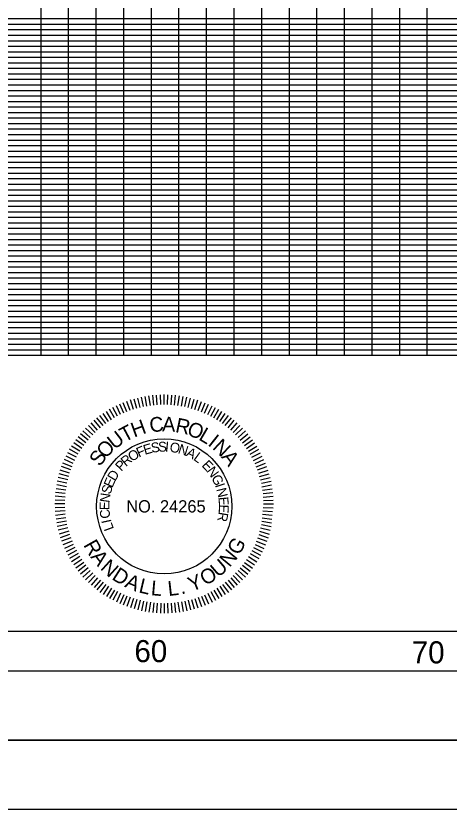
# Model space of a CAD drawing. Extents: x -15 to 165, y -6 to 109.
# Drawn here: x 135.09 to 150.79, y -6.45 to 22.3 of the extents above; entities that cross this region are included whole.
import ezdxf

# ---------------------------------------------------------------- set-up
doc = ezdxf.new("R2010")
doc.units = 0
for name, color, linetype in [('RD_SHT_Bndy', 7, 'Continuous'), ('RD_SHT_Iplotshp', 7, 'Continuous'), ('RD_SHT_MjGrid', 7, 'Continuous'), ('RD_SHT_MnGrid', 7, 'Continuous'), ('RD_SHT_SubGrid', 7, 'Continuous'), ('RD_SHT_TX', 7, 'Continuous'), ('RD_TX_PEShield', 7, 'Continuous')]:
    doc.layers.add(name, color=color, linetype=linetype)

msp = doc.modelspace()

# ---------------------------------------------------------------- linework, layer by layer
at = {"layer": 'RD_SHT_Bndy'}
for p, q in [((-12.73, -3.949), (163.27, -3.949)), ((-12.73, -6.449), (163.27, -6.449))]:
    msp.add_line(p, q, dxfattribs=at)
msp.add_lwpolyline([(-4.99, 103.551), (162.51, 103.551), (162.51, -1.449), (-4.99, -1.449)], close=True, dxfattribs=at)
at = {"layer": 'RD_SHT_Iplotshp'}
msp.add_lwpolyline([(-14.589, 106.051), (165.01, 106.051), (165.01, -3.949), (-14.589, -3.949)], close=True, dxfattribs=at)
at = {"layer": 'RD_SHT_MjGrid'}
for p, q in [((140, 10), (140, 100)), ((145, 10), (145, 100)), ((150, 10), (150, 100)), ((0, 20), (160, 20)), ((0, 15), (160, 15)), ((0, 10), (160, 10)), ((0, 0), (160, 0))]:
    msp.add_line(p, q, dxfattribs=at)
at = {"layer": 'RD_SHT_MnGrid'}
for p, q in [((136, 10), (136, 100)), ((137, 10), (137, 100)), ((138, 10), (138, 100)), ((139, 10), (139, 100)), ((141, 10), (141, 100)), ((142, 10), (142, 100)), ((143, 10), (143, 100)), ((144, 10), (144, 100)), ((146, 10), (146, 100)), ((147, 10), (147, 100)), ((148, 10), (148, 100)), ((149, 10), (149, 100)), ((0, 22), (160, 22)), ((0, 21), (160, 21)), ((0, 19), (160, 19)), ((0, 18), (160, 18)), ((0, 17), (160, 17)), ((0, 16), (160, 16)), ((0, 14), (160, 14)), ((0, 13), (160, 13)), ((0, 12), (160, 12)), ((0, 11), (160, 11))]:
    msp.add_line(p, q, dxfattribs=at)
at = {"layer": 'RD_SHT_SubGrid'}
for p, q in [((0, 22.2), (160, 22.2)), ((0, 21.8), (160, 21.8)), ((0, 21.6), (160, 21.6)), ((0, 21.4), (160, 21.4)), ((0, 21.2), (160, 21.2)), ((0, 20.8), (160, 20.8)), ((0, 20.6), (160, 20.6)), ((0, 20.4), (160, 20.4)), ((0, 20.2), (160, 20.2)), ((0, 19.8), (160, 19.8)), ((0, 19.6), (160, 19.6)), ((0, 19.4), (160, 19.4)), ((0, 19.2), (160, 19.2)), ((0, 18.8), (160, 18.8)), ((0, 18.6), (160, 18.6)), ((0, 18.4), (160, 18.4)), ((0, 18.2), (160, 18.2)), ((0, 17.8), (160, 17.8)), ((0, 17.6), (160, 17.6)), ((0, 17.4), (160, 17.4)), ((0, 17.2), (160, 17.2)), ((0, 16.8), (160, 16.8)), ((0, 16.6), (160, 16.6)), ((0, 16.4), (160, 16.4)), ((0, 16.2), (160, 16.2)), ((0, 15.8), (160, 15.8)), ((0, 15.6), (160, 15.6)), ((0, 15.4), (160, 15.4)), ((0, 15.2), (160, 15.2)), ((0, 14.8), (160, 14.8)), ((0, 14.6), (160, 14.6)), ((0, 14.4), (160, 14.4)), ((0, 14.2), (160, 14.2)), ((0, 13.8), (160, 13.8)), ((0, 13.6), (160, 13.6)), ((0, 13.4), (160, 13.4)), ((0, 13.2), (160, 13.2)), ((0, 12.8), (160, 12.8)), ((0, 12.6), (160, 12.6)), ((0, 12.4), (160, 12.4)), ((0, 12.2), (160, 12.2)), ((0, 11.8), (160, 11.8)), ((0, 11.6), (160, 11.6)), ((0, 11.4), (160, 11.4)), ((0, 11.2), (160, 11.2)), ((0, 10.8), (160, 10.8)), ((0, 10.6), (160, 10.6)), ((0, 10.4), (160, 10.4)), ((0, 10.2), (160, 10.2))]:
    msp.add_line(p, q, dxfattribs=at)
at = {"layer": 'RD_TX_PEShield'}
for p, q in [((139.349, 8.04), (139.239, 8.379)), ((139.349, 8.04), (139.239, 8.379)), ((139.47, 8.073), (139.372, 8.414)), ((139.47, 8.073), (139.372, 8.414)), ((139.592, 8.105), (139.506, 8.45)), ((139.592, 8.105), (139.506, 8.45)), ((139.713, 8.138), (139.639, 8.486)), ((139.713, 8.138), (139.639, 8.486)), ((139.838, 8.157), (139.776, 8.508)), ((139.838, 8.157), (139.776, 8.508)), ((139.962, 8.177), (139.912, 8.529)), ((139.962, 8.177), (139.912, 8.529)), ((140.086, 8.197), (140.049, 8.551)), ((140.086, 8.197), (140.049, 8.551)), ((140.212, 8.203), (140.187, 8.558)), ((140.212, 8.203), (140.187, 8.558)), ((140.337, 8.21), (140.325, 8.565)), ((140.337, 8.21), (140.325, 8.565)), ((140.463, 8.217), (140.463, 8.573)), ((140.463, 8.217), (140.463, 8.573)), ((140.588, 8.21), (140.601, 8.565)), ((140.588, 8.21), (140.601, 8.565)), ((140.714, 8.203), (140.739, 8.558)), ((140.714, 8.203), (140.739, 8.558)), ((140.84, 8.197), (140.877, 8.551)), ((140.84, 8.197), (140.877, 8.551)), ((140.964, 8.177), (141.013, 8.529)), ((140.964, 8.177), (141.013, 8.529)), ((141.088, 8.157), (141.15, 8.508)), ((141.088, 8.157), (141.15, 8.508)), ((141.212, 8.138), (141.286, 8.486)), ((141.212, 8.138), (141.286, 8.486)), ((141.212, 8.138), (141.286, 8.486)), ((141.334, 8.105), (141.42, 8.45)), ((141.334, 8.105), (141.42, 8.45)), ((141.334, 8.105), (141.42, 8.45)), ((141.455, 8.073), (141.553, 8.414)), ((141.455, 8.073), (141.553, 8.414)), ((141.455, 8.073), (141.553, 8.414)), ((141.577, 8.04), (141.687, 8.379)), ((141.577, 8.04), (141.687, 8.379)), ((141.577, 8.04), (141.687, 8.379)), ((138.773, 7.791), (138.606, 8.105)), ((138.773, 7.791), (138.606, 8.105)), ((138.885, 7.848), (138.729, 8.167)), ((138.885, 7.848), (138.729, 8.167)), ((138.997, 7.905), (138.852, 8.23)), ((138.997, 7.905), (138.852, 8.23)), ((139.114, 7.95), (138.981, 8.28)), ((139.114, 7.95), (138.981, 8.28)), ((139.231, 7.995), (139.11, 8.329)), ((139.231, 7.995), (139.11, 8.329)), ((141.694, 7.995), (141.816, 8.329)), ((141.694, 7.995), (141.816, 8.329)), ((141.694, 7.995), (141.816, 8.329)), ((141.811, 7.95), (141.945, 8.28)), ((141.811, 7.95), (141.945, 8.28)), ((141.811, 7.95), (141.945, 8.28)), ((141.929, 7.905), (142.074, 8.23)), ((141.929, 7.905), (142.074, 8.23)), ((141.929, 7.905), (142.074, 8.23)), ((142.041, 7.848), (142.197, 8.167)), ((142.041, 7.848), (142.197, 8.167)), ((142.041, 7.848), (142.197, 8.167)), ((142.153, 7.791), (142.32, 8.105)), ((142.153, 7.791), (142.32, 8.105)), ((142.153, 7.791), (142.32, 8.105)), ((138.344, 7.528), (138.135, 7.816)), ((138.344, 7.528), (138.135, 7.816)), ((138.45, 7.597), (138.251, 7.891)), ((138.45, 7.597), (138.251, 7.891)), ((138.555, 7.665), (138.367, 7.967)), ((138.555, 7.665), (138.367, 7.967)), ((138.661, 7.734), (138.483, 8.042)), ((138.661, 7.734), (138.483, 8.042)), ((142.265, 7.734), (142.443, 8.042)), ((142.265, 7.734), (142.443, 8.042)), ((142.265, 7.734), (142.443, 8.042)), ((142.371, 7.665), (142.559, 7.967)), ((142.371, 7.665), (142.559, 7.967)), ((142.371, 7.665), (142.559, 7.967)), ((142.476, 7.597), (142.675, 7.891)), ((142.476, 7.597), (142.675, 7.891)), ((142.476, 7.597), (142.675, 7.891)), ((142.581, 7.528), (142.791, 7.816)), ((142.581, 7.528), (142.791, 7.816)), ((142.581, 7.528), (142.791, 7.816)), ((138.051, 7.291), (137.813, 7.555)), ((138.051, 7.291), (137.813, 7.555)), ((138.149, 7.37), (137.92, 7.642)), ((138.149, 7.37), (137.92, 7.642)), ((138.246, 7.449), (138.027, 7.729)), ((138.246, 7.449), (138.027, 7.729)), ((142.679, 7.449), (142.898, 7.729)), ((142.679, 7.449), (142.898, 7.729)), ((142.679, 7.449), (142.898, 7.729)), ((142.777, 7.37), (143.005, 7.642)), ((142.777, 7.37), (143.005, 7.642)), ((142.777, 7.37), (143.005, 7.642)), ((142.875, 7.291), (143.113, 7.555)), ((142.875, 7.291), (143.113, 7.555)), ((142.875, 7.291), (143.113, 7.555)), ((137.784, 7.024), (137.52, 7.262)), ((137.784, 7.024), (137.52, 7.262)), ((137.873, 7.113), (137.617, 7.36)), ((137.873, 7.113), (137.617, 7.36)), ((137.962, 7.202), (137.715, 7.457)), ((137.962, 7.202), (137.715, 7.457)), ((142.964, 7.202), (143.211, 7.457)), ((142.964, 7.202), (143.211, 7.457)), ((142.964, 7.202), (143.211, 7.457)), ((143.052, 7.113), (143.308, 7.36)), ((143.052, 7.113), (143.308, 7.36)), ((143.052, 7.113), (143.308, 7.36)), ((143.141, 7.024), (143.406, 7.262)), ((143.141, 7.024), (143.406, 7.262)), ((143.141, 7.024), (143.406, 7.262)), ((137.547, 6.731), (137.259, 6.94)), ((137.547, 6.731), (137.259, 6.94)), ((137.626, 6.828), (137.346, 7.047)), ((137.626, 6.828), (137.346, 7.047)), ((137.705, 6.926), (137.433, 7.155)), ((137.705, 6.926), (137.433, 7.155)), ((143.221, 6.926), (143.493, 7.155)), ((143.221, 6.926), (143.493, 7.155)), ((143.221, 6.926), (143.493, 7.155)), ((143.3, 6.828), (143.58, 7.047)), ((143.3, 6.828), (143.58, 7.047)), ((143.3, 6.828), (143.58, 7.047)), ((143.379, 6.731), (143.667, 6.94)), ((143.379, 6.731), (143.667, 6.94)), ((143.379, 6.731), (143.667, 6.94)), ((137.41, 6.52), (137.108, 6.708)), ((137.41, 6.52), (137.108, 6.708)), ((137.478, 6.625), (137.183, 6.824)), ((137.478, 6.625), (137.183, 6.824)), ((143.447, 6.625), (143.742, 6.824)), ((143.447, 6.625), (143.742, 6.824)), ((143.447, 6.625), (143.742, 6.824)), ((143.516, 6.52), (143.817, 6.708)), ((143.516, 6.52), (143.817, 6.708)), ((143.516, 6.52), (143.817, 6.708)), ((137.227, 6.19), (136.907, 6.346)), ((137.227, 6.19), (136.907, 6.346)), ((137.284, 6.302), (136.97, 6.469)), ((137.284, 6.302), (136.97, 6.469)), ((137.341, 6.414), (137.033, 6.592)), ((137.341, 6.414), (137.033, 6.592)), ((143.584, 6.414), (143.893, 6.592)), ((143.584, 6.414), (143.893, 6.592)), ((143.584, 6.414), (143.893, 6.592)), ((143.641, 6.302), (143.955, 6.469)), ((143.641, 6.302), (143.955, 6.469)), ((143.641, 6.302), (143.955, 6.469)), ((143.699, 6.19), (144.018, 6.346)), ((143.699, 6.19), (144.018, 6.346)), ((143.699, 6.19), (144.018, 6.346)), ((137.125, 5.961), (136.795, 6.094)), ((137.125, 5.961), (136.795, 6.094)), ((137.17, 6.078), (136.845, 6.223)), ((137.17, 6.078), (136.845, 6.223)), ((143.756, 6.078), (144.081, 6.223)), ((143.756, 6.078), (144.081, 6.223)), ((143.756, 6.078), (144.081, 6.223)), ((143.801, 5.961), (144.13, 6.094)), ((143.801, 5.961), (144.13, 6.094)), ((143.801, 5.961), (144.13, 6.094)), ((137.035, 5.726), (136.696, 5.836)), ((137.035, 5.726), (136.696, 5.836)), ((137.08, 5.843), (136.746, 5.965)), ((137.08, 5.843), (136.746, 5.965)), ((143.846, 5.843), (144.18, 5.965)), ((143.846, 5.843), (144.18, 5.965)), ((143.846, 5.843), (144.18, 5.965)), ((143.891, 5.726), (144.229, 5.836)), ((143.891, 5.726), (144.229, 5.836)), ((143.891, 5.726), (144.229, 5.836)), ((136.97, 5.483), (136.625, 5.569)), ((136.97, 5.483), (136.625, 5.569)), ((137.002, 5.604), (136.66, 5.702)), ((137.002, 5.604), (136.66, 5.702)), ((143.923, 5.604), (144.265, 5.702)), ((143.923, 5.604), (144.265, 5.702)), ((143.923, 5.604), (144.265, 5.702)), ((143.956, 5.483), (144.301, 5.569)), ((143.956, 5.483), (144.301, 5.569)), ((143.956, 5.483), (144.301, 5.569)), ((136.917, 5.237), (136.567, 5.299)), ((136.917, 5.237), (136.567, 5.299)), ((136.937, 5.361), (136.589, 5.435)), ((136.937, 5.361), (136.589, 5.435)), ((143.988, 5.361), (144.337, 5.435)), ((143.988, 5.361), (144.337, 5.435)), ((143.988, 5.361), (144.337, 5.435)), ((144.008, 5.237), (144.358, 5.299)), ((144.008, 5.237), (144.358, 5.299)), ((144.008, 5.237), (144.358, 5.299)), ((136.871, 4.863), (136.517, 4.888)), ((136.871, 4.863), (136.517, 4.888)), ((136.878, 4.989), (136.524, 5.026)), ((136.878, 4.989), (136.524, 5.026)), ((136.898, 5.113), (136.546, 5.163)), ((136.898, 5.113), (136.546, 5.163)), ((144.028, 5.113), (144.38, 5.163)), ((144.028, 5.113), (144.38, 5.163)), ((144.028, 5.113), (144.38, 5.163)), ((144.048, 4.989), (144.402, 5.026)), ((144.048, 4.989), (144.402, 5.026)), ((144.048, 4.989), (144.402, 5.026)), ((144.054, 4.863), (144.409, 4.888)), ((144.054, 4.863), (144.409, 4.888)), ((144.054, 4.863), (144.409, 4.888)), ((136.858, 4.612), (136.502, 4.612)), ((136.858, 4.612), (136.502, 4.612)), ((136.865, 4.738), (136.509, 4.75)), ((136.865, 4.738), (136.509, 4.75)), ((144.061, 4.738), (144.416, 4.75)), ((144.061, 4.738), (144.416, 4.75)), ((144.061, 4.738), (144.416, 4.75)), ((144.067, 4.612), (144.423, 4.612)), ((144.067, 4.612), (144.423, 4.612)), ((144.067, 4.612), (144.423, 4.612)), ((136.865, 4.486), (136.509, 4.474)), ((136.865, 4.486), (136.509, 4.474)), ((136.871, 4.361), (136.517, 4.336)), ((136.871, 4.361), (136.517, 4.336)), ((144.041, 4.362), (144.394, 4.337)), ((144.041, 4.362), (144.394, 4.337)), ((144.054, 4.487), (144.409, 4.474)), ((144.054, 4.487), (144.409, 4.474)), ((136.878, 4.235), (136.524, 4.198)), ((136.878, 4.235), (136.524, 4.198)), ((136.898, 4.111), (136.546, 4.061)), ((136.898, 4.111), (136.546, 4.061)), ((144.015, 4.113), (144.366, 4.063)), ((144.015, 4.113), (144.366, 4.063)), ((144.028, 4.237), (144.38, 4.2)), ((144.028, 4.237), (144.38, 4.2)), ((136.917, 3.987), (136.567, 3.925)), ((136.917, 3.987), (136.567, 3.925)), ((136.937, 3.863), (136.589, 3.789)), ((136.937, 3.863), (136.589, 3.789)), ((136.97, 3.741), (136.625, 3.655)), ((136.97, 3.741), (136.625, 3.655)), ((143.956, 3.741), (144.301, 3.655)), ((143.956, 3.741), (144.301, 3.655)), ((143.988, 3.863), (144.337, 3.789)), ((143.988, 3.863), (144.337, 3.789)), ((144.002, 3.988), (144.351, 3.926)), ((144.002, 3.988), (144.351, 3.926)), ((137.002, 3.62), (136.66, 3.522)), ((137.002, 3.62), (136.66, 3.522)), ((137.035, 3.498), (136.696, 3.388)), ((143.891, 3.498), (144.229, 3.388)), ((143.891, 3.498), (144.229, 3.388)), ((143.923, 3.62), (144.265, 3.522)), ((143.923, 3.62), (144.265, 3.522)), ((137.08, 3.381), (136.746, 3.259)), ((137.08, 3.381), (136.746, 3.259)), ((137.125, 3.263), (136.795, 3.13)), ((137.125, 3.263), (136.795, 3.13)), ((143.801, 3.263), (144.13, 3.13)), ((143.801, 3.263), (144.13, 3.13)), ((143.846, 3.381), (144.18, 3.259)), ((143.846, 3.381), (144.18, 3.259)), ((137.17, 3.146), (136.845, 3.001)), ((137.17, 3.146), (136.845, 3.001)), ((137.227, 3.034), (136.907, 2.878)), ((137.227, 3.034), (136.907, 2.878)), ((137.284, 2.922), (136.97, 2.755)), ((137.284, 2.922), (136.97, 2.755)), ((143.641, 2.922), (143.955, 2.755)), ((143.641, 2.922), (143.955, 2.755)), ((143.699, 3.034), (144.018, 2.878)), ((143.699, 3.034), (144.018, 2.878)), ((143.756, 3.146), (144.081, 3.001)), ((143.756, 3.146), (144.081, 3.001)), ((137.341, 2.81), (137.033, 2.632)), ((137.341, 2.81), (137.033, 2.632)), ((137.41, 2.704), (137.108, 2.516)), ((137.41, 2.704), (137.108, 2.516)), ((137.478, 2.599), (137.183, 2.4)), ((137.478, 2.599), (137.183, 2.4)), ((143.447, 2.599), (143.742, 2.4)), ((143.447, 2.599), (143.742, 2.4)), ((143.516, 2.704), (143.817, 2.516)), ((143.516, 2.704), (143.817, 2.516)), ((143.584, 2.81), (143.893, 2.632)), ((143.584, 2.81), (143.893, 2.632)), ((137.547, 2.493), (137.259, 2.284)), ((137.547, 2.493), (137.259, 2.284)), ((137.626, 2.396), (137.346, 2.177)), ((137.626, 2.396), (137.346, 2.177)), ((143.3, 2.396), (143.58, 2.177)), ((143.3, 2.396), (143.58, 2.177)), ((143.379, 2.493), (143.667, 2.284)), ((143.379, 2.493), (143.667, 2.284)), ((137.705, 2.298), (137.433, 2.069)), ((137.705, 2.298), (137.433, 2.069)), ((137.784, 2.2), (137.52, 1.962)), ((137.784, 2.2), (137.52, 1.962)), ((137.873, 2.111), (137.617, 1.864)), ((137.873, 2.111), (137.617, 1.864)), ((137.962, 2.022), (137.715, 1.767)), ((137.962, 2.022), (137.715, 1.767)), ((142.964, 2.022), (143.211, 1.767)), ((142.964, 2.022), (143.211, 1.767)), ((143.052, 2.111), (143.308, 1.864)), ((143.052, 2.111), (143.308, 1.864)), ((143.141, 2.2), (143.406, 1.962)), ((143.141, 2.2), (143.406, 1.962)), ((143.221, 2.298), (143.493, 2.069)), ((143.221, 2.298), (143.493, 2.069)), ((138.051, 1.933), (137.813, 1.669)), ((138.051, 1.933), (137.813, 1.669)), ((138.149, 1.854), (137.92, 1.582)), ((138.149, 1.854), (137.92, 1.582)), ((138.246, 1.775), (138.027, 1.495)), ((138.246, 1.775), (138.027, 1.495)), ((142.679, 1.775), (142.898, 1.495)), ((142.679, 1.775), (142.898, 1.495)), ((142.777, 1.854), (143.005, 1.582)), ((142.777, 1.854), (143.005, 1.582)), ((142.875, 1.933), (143.113, 1.669)), ((138.344, 1.696), (138.135, 1.408)), ((138.344, 1.696), (138.135, 1.408)), ((138.45, 1.627), (138.251, 1.333)), ((138.45, 1.627), (138.251, 1.333)), ((138.555, 1.559), (138.367, 1.257)), ((138.555, 1.559), (138.367, 1.257)), ((138.661, 1.49), (138.483, 1.182)), ((138.661, 1.49), (138.483, 1.182)), ((142.265, 1.49), (142.443, 1.182)), ((142.265, 1.49), (142.443, 1.182)), ((142.371, 1.559), (142.559, 1.257)), ((142.371, 1.559), (142.559, 1.257)), ((142.476, 1.627), (142.675, 1.333)), ((142.476, 1.627), (142.675, 1.333)), ((142.581, 1.696), (142.791, 1.408)), ((142.581, 1.696), (142.791, 1.408)), ((138.773, 1.433), (138.606, 1.119)), ((138.773, 1.433), (138.606, 1.119)), ((138.885, 1.376), (138.729, 1.057)), ((138.885, 1.376), (138.729, 1.057)), ((138.997, 1.319), (138.852, 0.994)), ((138.997, 1.319), (138.852, 0.994)), ((139.114, 1.274), (138.981, 0.944)), ((139.114, 1.274), (138.981, 0.944)), ((139.231, 1.229), (139.11, 0.895)), ((139.231, 1.229), (139.11, 0.895)), ((139.349, 1.184), (139.239, 0.845)), ((139.349, 1.184), (139.239, 0.845)), ((139.47, 1.151), (139.372, 0.81)), ((139.47, 1.151), (139.372, 0.81)), ((141.455, 1.151), (141.553, 0.81)), ((141.455, 1.151), (141.553, 0.81)), ((141.577, 1.184), (141.687, 0.845)), ((141.577, 1.184), (141.687, 0.845)), ((141.694, 1.229), (141.816, 0.895)), ((141.694, 1.229), (141.816, 0.895)), ((141.811, 1.274), (141.945, 0.944)), ((141.811, 1.274), (141.945, 0.944)), ((141.929, 1.319), (142.074, 0.994)), ((141.929, 1.319), (142.074, 0.994)), ((142.041, 1.376), (142.197, 1.057)), ((142.041, 1.376), (142.197, 1.057)), ((142.153, 1.433), (142.32, 1.119)), ((142.153, 1.433), (142.32, 1.119)), ((139.592, 1.119), (139.506, 0.774)), ((139.592, 1.119), (139.506, 0.774)), ((139.713, 1.086), (139.639, 0.738)), ((139.713, 1.086), (139.639, 0.738)), ((139.838, 1.067), (139.776, 0.716)), ((139.838, 1.067), (139.776, 0.716)), ((139.962, 1.047), (139.912, 0.695)), ((139.962, 1.047), (139.912, 0.695)), ((140.086, 1.027), (140.049, 0.673)), ((140.086, 1.027), (140.049, 0.673)), ((140.212, 1.021), (140.187, 0.666)), ((140.212, 1.021), (140.187, 0.666)), ((140.337, 1.014), (140.325, 0.659)), ((140.337, 1.014), (140.325, 0.659)), ((140.463, 1.008), (140.463, 0.652)), ((140.463, 1.008), (140.463, 0.652)), ((140.588, 1.014), (140.601, 0.659)), ((140.588, 1.014), (140.601, 0.659)), ((140.714, 1.021), (140.739, 0.666)), ((140.714, 1.021), (140.739, 0.666)), ((140.84, 1.027), (140.877, 0.673)), ((140.84, 1.027), (140.877, 0.673)), ((140.964, 1.047), (141.013, 0.695)), ((140.964, 1.047), (141.013, 0.695)), ((141.088, 1.067), (141.15, 0.716)), ((141.088, 1.067), (141.15, 0.716)), ((141.212, 1.086), (141.286, 0.738)), ((141.212, 1.086), (141.286, 0.738)), ((141.334, 1.119), (141.42, 0.774)), ((141.334, 1.119), (141.42, 0.774))]:
    msp.add_line(p, q, dxfattribs=at)
msp.add_circle((140.463, 4.524), 2.448, dxfattribs=at)

# ---------------------------------------------------------------- texts
at = {"layer": 'RD_SHT_TX'}
for s, p in [('60', (139.385, -1.123)), ('70', (149.438, -1.167))]:
    msp.add_text(s, height=0.8, dxfattribs=at).set_placement(p)
at = {"layer": 'RD_TX_PEShield'}
for s, height, rotation, p in [('C', 0.534, 6.8832, (139.962, 7.198)), ('A', 0.534, 357.9448, (140.384, 7.243)), ('T', 0.534, 28.0947, (139.029, 6.836)), ('H', 0.534, 19.9102, (139.372, 7.016)), ('R', 0.534, 348.267, (140.842, 7.218)), ('O', 0.534, 339.3286, (141.256, 7.126)), ('U', 0.534, 37.7726, (138.661, 6.562)), ('L', 0.534, 329.6507, (141.682, 6.956)), ('I', 0.534, 321.4663, (142.016, 6.758)), ('N', 0.534, 317.0007, (142.185, 6.63)), ('O', 0.534, 47.4504, (138.344, 6.23)), ('F', 0.356, 23.0853, (139.544, 6.29)), ('E', 0.356, 16.1843, (139.763, 6.388)), ('S', 0.356, 8.6909, (140.012, 6.463)), ('S', 0.356, 1.79, (140.248, 6.503)), ('I', 0.356, 354.889, (140.487, 6.515)), ('O', 0.356, 350.4045, (140.643, 6.507)), ('N', 0.356, 341.7029, (140.941, 6.457)), ('A', 0.356, 333.0013, (141.227, 6.362)), ('S', 0.534, 54.9027, (138.14, 5.941)), ('R', 0.356, 39.8902, (139.072, 5.949)), ('O', 0.356, 31.7869, (139.287, 6.131)), ('L', 0.356, 324.2997, (141.497, 6.225)), ('A', 0.534, 307.3229, (142.514, 6.31)), ('P', 0.356, 46.7912, (138.911, 5.771)), ('E', 0.356, 313.2251, (141.804, 5.995)), ('D', 0.356, 59.074, (138.682, 5.413)), ('N', 0.356, 305.7317, (141.984, 5.808)), ('E', 0.356, 66.5674, (138.581, 5.173)), ('G', 0.356, 297.0301, (142.161, 5.563)), ('S', 0.356, 73.4683, (138.517, 4.942)), ('I', 0.356, 288.3285, (142.299, 5.294)), ('N', 0.356, 283.8441, (142.353, 5.148)), ('N', 0.356, 82.17, (138.476, 4.643)), ('E', 0.356, 89.6633, (138.477, 4.383)), ('E', 0.356, 275.1424, (142.426, 4.855)), ('C', 0.356, 97.7667, (138.517, 4.104)), ('E', 0.356, 267.6491, (142.452, 4.596)), ('I', 0.356, 102.2511, (138.556, 3.953)), ('R', 0.356, 260.1557, (142.444, 4.336)), ('L', 0.356, 109.7445, (138.646, 3.71)), ('R', 0.534, 299.1493, (137.523, 3.127)), ('G', 0.534, 60.1113, (143.174, 2.722)), ('N', 0.534, 50.4335, (142.832, 2.292)), ('A', 0.534, 308.0877, (137.775, 2.687)), ('N', 0.534, 317.7655, (138.122, 2.261)), ('U', 0.534, 40.7556, (142.423, 1.925)), ('D', 0.534, 327.4433, (138.536, 1.9)), ('A', 0.534, 337.1212, (139.005, 1.614)), ('Y', 0.534, 21.4, (141.451, 1.422)), ('O', 0.534, 31.0778, (141.958, 1.633)), ('L', 0.534, 346.799, (139.515, 1.41)), ('L', 0.534, 354.9835, (139.968, 1.307)), ('L', 0.534, 6.5171, (140.621, 1.273)), ('.', 0.534, 14.7016, (141.082, 1.328))]:
    msp.add_text(s, height=height, rotation=rotation, dxfattribs=at).set_placement(p)
msp.add_text('NO. 24265', height=0.445, dxfattribs=at).set_placement((139.087, 4.302))

doc.saveas('drawing.dxf')
